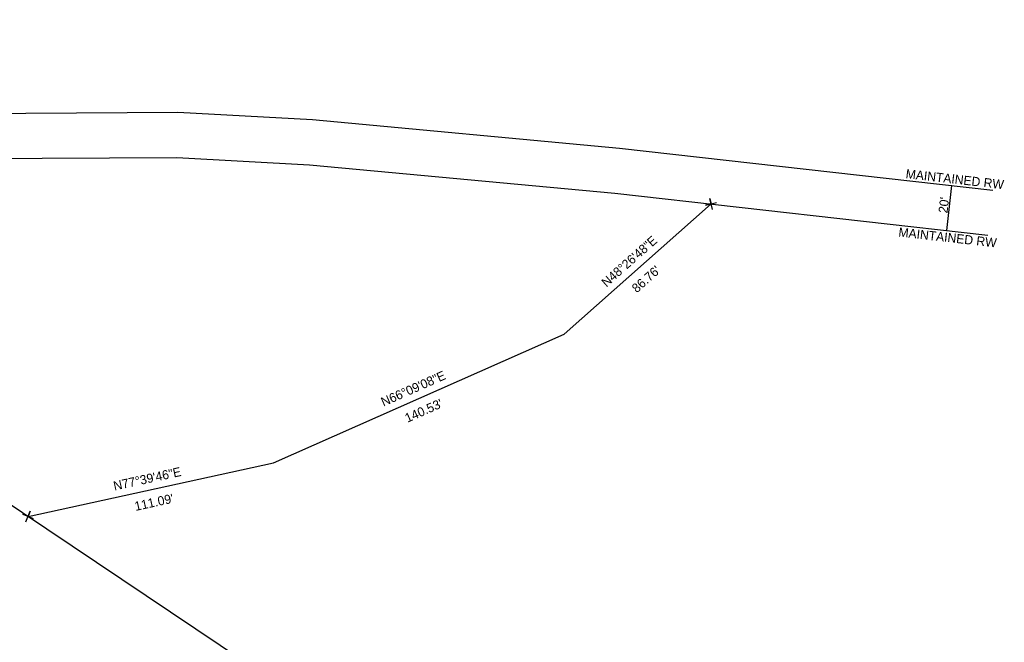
# Model space of a CAD drawing. Extents: x 831731 to 833706, y 722402 to 726085.
# Drawn here: x 832985.8 to 833421.2, y 723991.4 to 724266.5 of the extents above; entities that cross this region are included whole.
import ezdxf

# ---------------------------------------------------------------- set-up
doc = ezdxf.new("R2010")
doc.units = 0
for name, color, linetype in [('Exist Property Corner CELL', 7, 'Continuous'), ('Exist Property Line', 7, 'Continuous'), ('Exist Property Text', 7, 'Continuous'), ('Exist Right of Way Line', 7, 'Continuous'), ('Exist Right of Way Text', 7, 'Continuous'), ('Exist Right of Way Width CELL', 7, 'Continuous')]:
    doc.layers.add(name, color=color, linetype=linetype)

msp = doc.modelspace()

# ---------------------------------------------------------------- linework, layer by layer
at = {"layer": 'Exist Property Corner CELL'}
for p, q in [((833291.5, 724185.14), (833291.5, 724185.14)), ((832989.52, 724047.04), (832989.52, 724047.04))]:
    msp.add_line(p, q, dxfattribs=at)
for points in [[(833292.08, 724182.71), (833290.93, 724187.57), (833291.5, 724185.14), (833289.07, 724184.57), (833293.94, 724185.71)], [(832988.6, 724044.72), (832990.45, 724049.36), (832989.52, 724047.04), (832987.2, 724047.97), (832991.85, 724046.11)]]:
    msp.add_lwpolyline(points, dxfattribs=at)
at = {"layer": 'Exist Property Line'}
for p, q in [((833226.58, 724127.59), (833291.5, 724185.14)), ((833098.05, 724070.78), (833226.58, 724127.59)), ((832989.52, 724047.04), (833098.05, 724070.78))]:
    msp.add_line(p, q, dxfattribs=at)
at = {"layer": 'Exist Right of Way Line'}
for points in [[(832651.87, 724266.54), (832803.02, 724237.13), (832873.34, 724226.96), (832965.95, 724225.16), (833055.76, 724225.65), (833115.36, 724222.4), (833251.07, 724209.81), (833416.13, 724191.27)], [(832648.05, 724246.91), (832799.67, 724217.41), (832871.71, 724206.99), (832965.81, 724205.16), (833055.27, 724205.65), (833113.9, 724202.45), (833249.03, 724189.91), (833413.9, 724171.4)], [(832829.84, 724151.68), (832904, 724110.25), (832928.25, 724093.21), (832964.9, 724063.53), (833118.37, 723960.76)]]:
    msp.add_lwpolyline(points, dxfattribs=at)
at = {"layer": 'Exist Right of Way Width CELL'}
msp.add_line((833395.77, 724173.43), (833398, 724193.31), dxfattribs=at)
msp.add_lwpolyline([(833398, 724193.31), (833397.97, 724193.05), (833397.87, 724193.29)], dxfattribs=at)

# ---------------------------------------------------------------- texts
at = {"layer": 'Exist Property Text'}
for s, rotation, p in [('N48°26\'48"E', 41.5532, (833245.25, 724148.15)), ("86.76'", 41.5532, (833258.66, 724145.6)), ('N66°09\'08"E', 23.8479, (833146.67, 724095.55)), ("140.53'", 23.8479, (833157.25, 724088.42)), ('N77°39\'46"E', 12.3372, (833027.73, 724058.47)), ("111.09'", 12.3372, (833037.08, 724049.46))]:
    msp.add_text(s, height=4.02, rotation=rotation, dxfattribs=at).set_placement(p)
at = {"layer": 'Exist Right of Way Text'}
for s, rotation, p in [('MAINTAINED RW', 353.5933, (833377.41, 724196.52)), ("20'", 83.3422, (833396.01, 724180.88)), ('MAINTAINED RW', 353.5933, (833374.21, 724170.76))]:
    msp.add_text(s, height=4.02, rotation=rotation, dxfattribs=at).set_placement(p)

doc.saveas('drawing.dxf')
